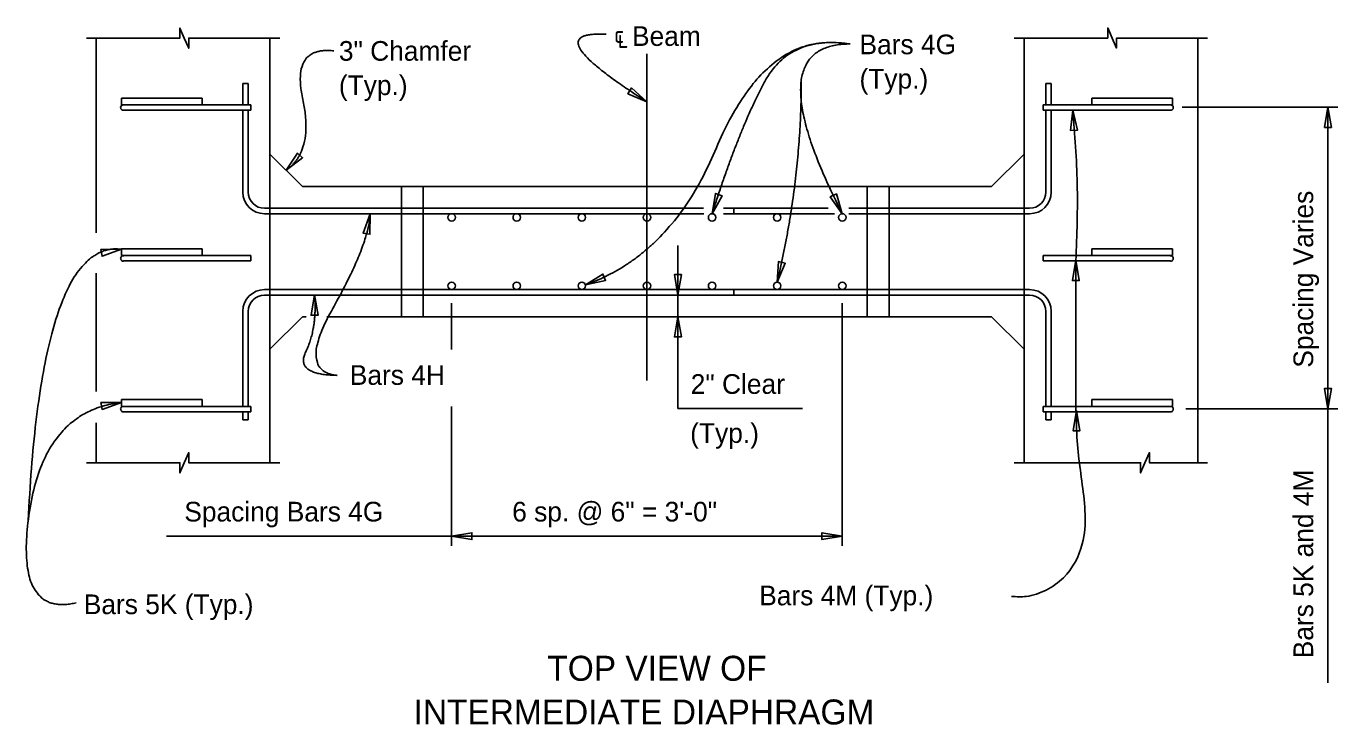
# Model space of a CAD drawing. Extents: x 0.4 to 30.8, y 0.6 to 19.4.
# Drawn here: x 0.87 to 10.94, y 13.29 to 18.66 of the extents above; entities that cross this region are included whole.
import ezdxf

# ---------------------------------------------------------------- set-up
doc = ezdxf.new("R2010")
doc.units = 0
for name, color, linetype in [('BeamConc', 7, 'Continuous'), ('CL_Major', 7, 'Continuous'), ('Dimension', 7, 'Continuous'), ('Miscellaneous', 7, 'Continuous'), ('Rebar', 7, 'Continuous'), ('TextStructures', 7, 'Continuous')]:
    doc.layers.add(name, color=color, linetype=linetype)

msp = doc.modelspace()

# ---------------------------------------------------------------- linework, layer by layer
at = {"layer": 'BeamConc'}
for p, q in [((1.405, 17.069), (1.405, 18.566)), ((2.738, 15.303), (2.738, 18.566)), ((8.53, 18.566), (8.53, 15.303)), ((9.863, 18.566), (9.863, 15.303)), ((2.988, 17.425), (2.738, 17.675)), ((8.53, 17.675), (8.28, 17.425)), ((8.28, 17.425), (2.988, 17.425)), ((1.405, 15.85), (1.405, 16.759)), ((2.988, 16.425), (2.738, 16.175)), ((3.016, 16.425), (2.988, 16.425)), ((8.28, 16.425), (3.175, 16.425)), ((8.53, 16.175), (8.28, 16.425)), ((1.405, 15.303), (1.405, 15.609))]:
    msp.add_line(p, q, dxfattribs=at)
at = {"layer": 'CL_Major'}
msp.add_line((5.634, 15.935), (5.634, 18.446), dxfattribs=at)
at = {"layer": 'Dimension'}
for p, q in [((9.744, 18.035), (10.939, 18.035)), ((10.863, 18.035), (10.863, 13.61)), ((5.872, 16.972), (5.872, 15.719)), ((4.134, 16.528), (4.134, 16.174)), ((7.134, 16.528), (7.134, 14.663)), ((4.134, 15.734), (4.134, 14.663)), ((5.872, 15.719), (6.828, 15.719)), ((9.771, 15.718), (10.939, 15.718)), ((1.945, 14.738), (7.134, 14.738))]:
    msp.add_line(p, q, dxfattribs=at)
for points in [[(2.814, 18.566), (2.115, 18.566), (2.115, 18.488), (2.081, 18.566), (2.047, 18.643), (2.047, 18.566), (1.329, 18.566)], [(9.939, 18.566), (9.24, 18.566), (9.24, 18.489), (9.206, 18.566), (9.172, 18.644), (9.172, 18.566), (8.454, 18.566)], [(2.814, 15.303), (2.115, 15.303), (2.115, 15.38), (2.081, 15.303), (2.047, 15.225), (2.047, 15.303), (1.329, 15.303)], [(9.939, 15.303), (9.492, 15.303), (9.492, 15.38), (9.458, 15.303), (9.424, 15.225), (9.424, 15.303), (8.454, 15.303)]]:
    msp.add_lwpolyline(points, dxfattribs=at)
for points in [[(5.634, 18.077), (5.516, 18.183), (5.488, 18.138)], [(10.863, 18.035), (10.89, 17.879), (10.837, 17.879)], [(8.904, 18.013), (8.887, 17.855), (8.94, 17.858)], [(2.863, 17.55), (2.951, 17.682), (2.989, 17.646)], [(6.134, 17.216), (6.161, 17.372), (6.211, 17.355)], [(7.134, 17.216), (7.041, 17.345), (7.089, 17.368)], [(3.509, 17.216), (3.454, 17.068), (3.506, 17.058)], [(3.509, 17.216), (3.509, 17.216), (3.509, 17.216)], [(1.599, 16.943), (1.441, 16.942), (1.45, 16.89)], [(6.634, 16.69), (6.696, 16.836), (6.644, 16.848)], [(8.928, 16.859), (8.901, 16.703), (8.954, 16.703)], [(5.162, 16.67), (5.316, 16.704), (5.296, 16.753)], [(5.872, 16.591), (5.898, 16.748), (5.845, 16.748)], [(3.082, 16.592), (3.108, 16.436), (3.055, 16.436)], [(5.872, 16.425), (5.845, 16.269), (5.898, 16.269)], [(10.863, 15.718), (10.837, 15.874), (10.89, 15.874)], [(1.599, 15.766), (1.441, 15.765), (1.45, 15.713)], [(8.932, 15.705), (8.906, 15.548), (8.959, 15.548)], [(8.932, 15.705), (8.932, 15.704), (8.932, 15.704)], [(4.134, 14.738), (4.29, 14.765), (4.29, 14.712)], [(7.134, 14.738), (6.978, 14.712), (6.978, 14.765)]]:
    msp.add_lwpolyline(points, close=True, dxfattribs=at)
for points in [[(5.634, 18.077), (4.768, 18.625), (5.321, 18.595)], [(6.134, 17.216), (6.339, 17.859), (6.73, 18.591), (7.195, 18.521)], [(2.863, 17.55), (3.077, 17.701), (2.903, 18.503), (3.228, 18.468)], [(5.162, 16.67), (5.823, 16.905), (6.49, 18.495), (6.985, 18.529)], [(7.134, 17.216), (6.465, 18.521), (7.195, 18.521)], [(6.634, 16.69), (6.819, 17.473), (6.819, 18.24)], [(3.509, 17.216), (3.495, 16.974), (2.948, 16.004), (3.254, 15.974)], [(1.599, 16.943), (0.986, 17.02), (0.882, 14.859)], [(3.082, 16.591), (3.101, 16.334), (2.927, 15.979), (3.254, 15.974)], [(1.599, 15.766), (1.001, 15.7), (0.777, 14.116), (1.251, 14.226)]]:
    msp.add_open_spline(points, degree=2, dxfattribs=at)
for points in [[(8.904, 18.013), (8.938, 17.446), (8.928, 16.857)], [(8.928, 16.859), (8.928, 16.322), (8.928, 15.694)], [(8.932, 15.705), (8.932, 15.583), (8.977, 15.134), (8.977, 14.679), (8.833, 14.419), (8.699, 14.324), (8.546, 14.275), (8.434, 14.275)]]:
    msp.add_spline(points, degree=3, dxfattribs=at)
at = {"layer": 'Miscellaneous'}
for p, q in [((3.748, 17.425), (3.748, 16.425)), ((3.915, 17.425), (3.915, 16.425)), ((7.326, 17.425), (7.326, 16.425)), ((7.493, 17.425), (7.493, 16.425))]:
    msp.add_line(p, q, dxfattribs=at)
at = {"layer": 'Rebar'}
for p, q in [((2.53, 18.216), (2.572, 18.216)), ((2.53, 18.053), (2.53, 18.216)), ((2.572, 18.053), (2.572, 18.216)), ((8.738, 18.216), (8.697, 18.216)), ((8.697, 18.216), (8.697, 18.053)), ((8.738, 18.216), (8.738, 18.053)), ((1.599, 18.053), (1.599, 18.105)), ((1.599, 18.105), (2.219, 18.105)), ((1.599, 18.053), (2.592, 18.053)), ((2.219, 18.053), (2.219, 18.105)), ((2.592, 18.011), (2.592, 18.053)), ((9.669, 18.053), (8.676, 18.053)), ((8.676, 18.011), (8.676, 18.053)), ((9.669, 18.105), (9.049, 18.105)), ((9.049, 18.053), (9.049, 18.105)), ((9.669, 18.053), (9.669, 18.105)), ((1.613, 18.011), (2.592, 18.011)), ((2.53, 17.383), (2.53, 18.011)), ((2.572, 17.383), (2.572, 18.011)), ((9.655, 18.011), (8.676, 18.011)), ((8.697, 18.011), (8.697, 17.383)), ((8.738, 18.011), (8.738, 17.383)), ((6.068, 17.258), (2.697, 17.258)), ((7.025, 17.258), (6.221, 17.258)), ((6.301, 17.216), (6.301, 17.258)), ((8.572, 17.258), (7.185, 17.258)), ((6.071, 17.216), (2.696, 17.216)), ((7.075, 17.216), (6.221, 17.216)), ((8.572, 17.216), (7.185, 17.216)), ((1.599, 16.894), (1.599, 16.946)), ((1.599, 16.946), (2.219, 16.946)), ((2.219, 16.894), (2.219, 16.946)), ((9.669, 16.946), (9.049, 16.946)), ((9.049, 16.894), (9.049, 16.946)), ((9.669, 16.894), (9.669, 16.946)), ((1.599, 16.894), (2.592, 16.894)), ((1.613, 16.853), (2.592, 16.853)), ((2.592, 16.853), (2.592, 16.894)), ((9.669, 16.894), (8.676, 16.894)), ((8.676, 16.853), (8.676, 16.894)), ((9.655, 16.853), (8.676, 16.853)), ((8.572, 16.633), (2.696, 16.633)), ((6.301, 16.591), (6.301, 16.633)), ((8.572, 16.591), (2.697, 16.591)), ((2.53, 16.467), (2.53, 15.736)), ((2.572, 16.466), (2.572, 15.736)), ((8.697, 15.736), (8.697, 16.466)), ((8.738, 15.736), (8.738, 16.467)), ((1.599, 15.736), (1.599, 15.788)), ((1.599, 15.788), (2.219, 15.788)), ((1.599, 15.736), (2.592, 15.736)), ((2.219, 15.736), (2.219, 15.788)), ((2.592, 15.694), (2.592, 15.736)), ((9.669, 15.736), (8.676, 15.736)), ((8.676, 15.694), (8.676, 15.736)), ((9.669, 15.788), (9.049, 15.788)), ((9.049, 15.736), (9.049, 15.788)), ((9.669, 15.736), (9.669, 15.788)), ((1.613, 15.694), (2.592, 15.694)), ((2.53, 15.694), (2.53, 15.633)), ((2.53, 15.633), (2.572, 15.633)), ((2.572, 15.694), (2.572, 15.633)), ((9.655, 15.694), (8.676, 15.694)), ((8.697, 15.633), (8.697, 15.694)), ((8.738, 15.633), (8.697, 15.633)), ((8.738, 15.633), (8.738, 15.694))]:
    msp.add_line(p, q, dxfattribs=at)
for centre in [(4.134, 17.188), (4.634, 17.188), (5.134, 17.188), (5.634, 17.188), (6.134, 17.188), (6.634, 17.188), (7.134, 17.188), (4.134, 16.662), (4.634, 16.662), (5.134, 16.662), (5.634, 16.662), (6.134, 16.662), (6.634, 16.662), (7.134, 16.662)]:
    msp.add_circle(centre, 0.0286, dxfattribs=at)
for centre, radius, start, end in [((1.613, 18.032), 0.0209, 81.4319, 269.9425), ((9.655, 18.032), 0.0209, 270.0575, 98.5681), ((2.697, 17.383), 0.167, 180, 270), ((2.697, 17.383), 0.125, 180, 270), ((8.572, 17.383), 0.125, 270, 360), ((8.572, 17.383), 0.167, 270, 360), ((1.613, 16.873), 0.0209, 81.4319, 269.9425), ((9.655, 16.873), 0.0209, 270.0575, 98.5681), ((2.697, 16.466), 0.167, 90, 180), ((8.572, 16.466), 0.167, 0, 90), ((2.697, 16.466), 0.125, 90, 180), ((8.572, 16.466), 0.125, 0, 90), ((1.613, 15.715), 0.0209, 81.4319, 269.9425), ((9.655, 15.715), 0.0209, 270.0575, 98.5681)]:
    msp.add_arc(centre, radius, start, end, dxfattribs=at)

# ---------------------------------------------------------------- texts
at = {"layer": 'Dimension'}
for s, height, p in [('3" Chamfer', 0.1512, (3.268, 18.392)), ('Bars 4G', 0.1512, (7.266, 18.442)), ('(Typ.)', 0.1512, (7.266, 18.178)), ('(Typ.)', 0.1512, (3.268, 18.128)), ('TOP VIEW OF', 0.192, (4.869, 13.627)), ('INTERMEDIATE DIAPHRAGM', 0.192, (3.842, 13.291))]:
    msp.add_text(s, height=height, dxfattribs=at).set_placement(p)
at = {"layer": 'TextStructures'}
for s, p in [('℄ Beam', (5.381, 18.506)), ('Bars 4H', (3.352, 15.901)), ('2" Clear', (5.97, 15.832)), ('(Typ.)', (5.966, 15.455)), ('Spacing Bars 4G', (2.081, 14.851)), ('6 sp. @ 6" = 3\'-0"', (4.599, 14.851)), ('Bars 4M (Typ.)', (6.496, 14.207)), ('Bars 5K (Typ.)', (1.309, 14.139))]:
    msp.add_text(s, height=0.1512, dxfattribs=at).set_placement(p)
for s, p in [('Spacing Varies', (10.75, 16.033)), ('Bars 5K and 4M', (10.75, 13.8))]:
    msp.add_text(s, height=0.1512, rotation=90, dxfattribs=at).set_placement(p)

doc.saveas('drawing.dxf')
